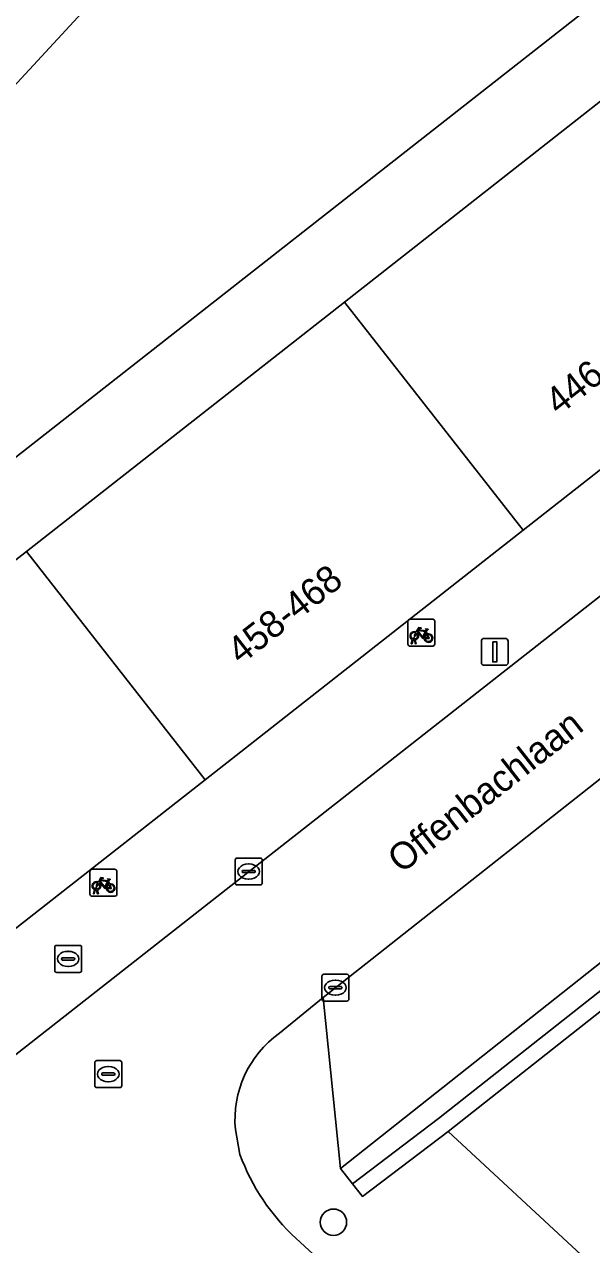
# Model space of a CAD drawing. Extents: x 159217 to 160349, y 381246 to 382172.
# Drawn here: x 159639.79 to 159660.85, y 381595.69 to 381640.95 of the extents above; entities that cross this region are included whole.
import ezdxf

# ---------------------------------------------------------------- set-up
doc = ezdxf.new("R2010")
doc.units = 0
for name, color, linetype in [('IMGEO_Boom', 7, 'Continuous'), ('IMGEO_Brandkraan', 7, 'Continuous'), ('IMGEO_Fietsenrek', 7, 'Continuous'), ('IMGEO_Groenvoorziening', 7, 'Continuous'), ('IMGEO_Haag', 7, 'Continuous'), ('IMGEO_Kolk', 7, 'Continuous'), ('IMGEO_Lichtmast', 7, 'Continuous'), ('IMGEO_Openbare_ruimte_label', 7, 'Continuous'), ('IMGEO_Pand', 7, 'Continuous'), ('IMGEO_Pand_nummerreeks', 7, 'Continuous'), ('IMGEO_Parkeervlak_open', 7, 'Continuous'), ('IMGEO_Rijbaan_lokaal_open', 7, 'Continuous'), ('IMGEO_Rioolput', 7, 'Continuous'), ('IMGEO_Voetpad_open', 7, 'Continuous')]:
    doc.layers.add(name, color=color, linetype=linetype)

msp = doc.modelspace()

# ---------------------------------------------------------------- linework, layer by layer
at = {"layer": 'IMGEO_Boom'}
msp.add_circle((159651.269, 381596.525), 0.489, dxfattribs=at)
at = {"layer": 'IMGEO_Brandkraan'}
for p, q in [((159640.919, 381605.866), (159640.919, 381606.718)), ((159640.994, 381606.792), (159641.846, 381606.792)), ((159641.407, 381606.572), (159641.432, 381606.572)), ((159641.92, 381606.718), (159641.92, 381605.866)), ((159641.178, 381606.286), (159641.178, 381606.298)), ((159641.616, 381606.249), (159641.218, 381606.249)), ((159641.221, 381606.335), (159641.619, 381606.335)), ((159641.662, 381606.298), (159641.662, 381606.286)), ((159641.846, 381605.792), (159640.994, 381605.792)), ((159641.43, 381606.012), (159641.405, 381606.012))]:
    msp.add_line(p, q, dxfattribs=at)
for points in [[(159640.919, 381605.866), (159640.919, 381606.718)], [(159640.994, 381606.792), (159641.846, 381606.792)], [(159641.92, 381606.718), (159641.92, 381605.866)], [(159641.846, 381605.792), (159640.994, 381605.792)]]:
    msp.add_lwpolyline(points, dxfattribs=at)
for centre, radius, start, end in [((159640.996, 381606.716), 0.0765, 91.552, 178.448), ((159640.996, 381606.716), 0.0765, 91.552, 178.448), ((159641.844, 381606.716), 0.0765, 1.552, 88.448), ((159641.844, 381606.716), 0.0765, 1.552, 88.448), ((159641.218, 381606.295), 0.0403, 85.8775, 175.7526), ((159641.215, 381606.285), 0.0366, 178.938, 274.7102), ((159641.619, 381606.292), 0.043, 264.8664, 352.4533), ((159641.623, 381606.297), 0.0386, 1.7309, 96.639), ((159640.996, 381605.868), 0.0765, 181.552, 268.448), ((159640.996, 381605.868), 0.0765, 181.552, 268.448), ((159641.844, 381605.868), 0.0765, 271.552, 358.448), ((159641.844, 381605.868), 0.0765, 271.552, 358.448)]:
    msp.add_arc(centre, radius, start, end, dxfattribs=at)
for centre, major_axis, ratio, start_param, end_param in [((159641.406, 381606.292), (-0.387, 0.002), 0.722429, 4.712389, 7.853982), ((159641.431, 381606.292), (-0.39, 0.002), 0.717154, 1.570796, 4.712389)]:
    msp.add_ellipse(centre, major_axis=major_axis, ratio=ratio, start_param=start_param, end_param=end_param, dxfattribs=at)
at = {"layer": 'IMGEO_Fietsenrek'}
for p, q in [((159654.03, 381617.966), (159654.03, 381618.807)), ((159654.03, 381618.807), (159654.03, 381617.966)), ((159654.105, 381618.891), (159654.946, 381618.891)), ((159654.946, 381618.891), (159654.105, 381618.891)), ((159655.03, 381618.816), (159655.03, 381617.975)), ((159655.03, 381617.975), (159655.03, 381618.816)), ((159654.717, 381618.44), (159654.753, 381618.345)), ((159654.955, 381617.891), (159654.114, 381617.891)), ((159654.114, 381617.891), (159654.955, 381617.891)), ((159654.157, 381617.975), (159654.196, 381618.135)), ((159654.191, 381617.975), (159654.157, 381617.975)), ((159654.226, 381618.123), (159654.191, 381617.975)), ((159654.268, 381618.147), (159654.267, 381618.151)), ((159654.309, 381617.975), (159654.275, 381618.117)), ((159654.299, 381618.158), (159654.3, 381618.151)), ((159654.307, 381618.121), (159654.342, 381617.975)), ((159654.342, 381617.975), (159654.309, 381617.975)), ((159642.228, 381608.692), (159642.228, 381609.533)), ((159642.228, 381609.533), (159642.228, 381608.692)), ((159642.303, 381609.617), (159643.144, 381609.617)), ((159643.144, 381609.617), (159642.303, 381609.617)), ((159643.228, 381609.542), (159643.228, 381608.701)), ((159643.228, 381608.701), (159643.228, 381609.542)), ((159642.355, 381608.701), (159642.394, 381608.861)), ((159642.424, 381608.849), (159642.389, 381608.701)), ((159642.466, 381608.873), (159642.465, 381608.877)), ((159642.507, 381608.701), (159642.473, 381608.843)), ((159642.497, 381608.884), (159642.498, 381608.877)), ((159642.505, 381608.847), (159642.54, 381608.701)), ((159642.915, 381609.166), (159642.951, 381609.071)), ((159643.153, 381608.617), (159642.312, 381608.617)), ((159642.312, 381608.617), (159643.153, 381608.617)), ((159642.389, 381608.701), (159642.355, 381608.701)), ((159642.54, 381608.701), (159642.507, 381608.701))]:
    msp.add_line(p, q, dxfattribs=at)
for points in [[(159654.364, 381618.365), (159654.312, 381618.275), (159654.272, 381618.25), (159654.273, 381618.297), (159654.328, 381618.391)], [(159654.343, 381618.417), (159654.438, 381618.581), (159654.524, 381618.567), (159654.526, 381618.558), (159654.47, 381618.547), (159654.443, 381618.502), (159654.699, 381618.461)], [(159654.639, 381618.173), (159654.589, 381618.173), (159654.398, 381618.424), (159654.379, 381618.392)], [(159654.686, 381618.436), (159654.429, 381618.477), (159654.412, 381618.448), (159654.579, 381618.228), (159654.686, 381618.436)], [(159654.734, 381618.338), (159654.704, 381618.415), (159654.595, 381618.197), (159654.638, 381618.197)], [(159654.668, 381618.197), (159654.788, 381618.196), (159654.744, 381618.31)], [(159654.764, 381618.317), (159654.819, 381618.172), (159654.669, 381618.172)], [(159654.699, 381618.461), (159654.724, 381618.51), (159654.718, 381618.514), (159654.695, 381618.518), (159654.683, 381618.525), (159654.682, 381618.528), (159654.684, 381618.533), (159654.779, 381618.518), (159654.781, 381618.508), (159654.771, 381618.495), (159654.759, 381618.489), (159654.745, 381618.495), (159654.717, 381618.44)], [(159642.541, 381609.143), (159642.636, 381609.307), (159642.722, 381609.293), (159642.724, 381609.284), (159642.668, 381609.273), (159642.641, 381609.228), (159642.897, 381609.187)], [(159642.884, 381609.162), (159642.627, 381609.203), (159642.61, 381609.174), (159642.777, 381608.954), (159642.884, 381609.162)], [(159642.897, 381609.187), (159642.922, 381609.236), (159642.916, 381609.24), (159642.893, 381609.244), (159642.881, 381609.251), (159642.88, 381609.254), (159642.882, 381609.259), (159642.977, 381609.244), (159642.979, 381609.234), (159642.969, 381609.221), (159642.957, 381609.215), (159642.943, 381609.221), (159642.915, 381609.166)], [(159642.562, 381609.091), (159642.51, 381609.001), (159642.47, 381608.976), (159642.471, 381609.023), (159642.526, 381609.117)], [(159642.837, 381608.899), (159642.787, 381608.899), (159642.596, 381609.15), (159642.577, 381609.118)], [(159642.932, 381609.064), (159642.902, 381609.141), (159642.793, 381608.923), (159642.836, 381608.923)], [(159642.866, 381608.923), (159642.986, 381608.922), (159642.942, 381609.036)], [(159642.962, 381609.043), (159643.017, 381608.898), (159642.867, 381608.898)]]:
    msp.add_lwpolyline(points, dxfattribs=at)
for centre, radius, start, end in [((159654.108, 381618.813), 0.0779, 92.4484, 184.2845), ((159654.108, 381618.813), 0.0779, 92.4484, 184.2845), ((159654.952, 381618.813), 0.0779, 2.4484, 94.2845), ((159654.952, 381618.813), 0.0779, 2.4484, 94.2845), ((159654.27, 381618.276), 0.159, 62.6766, 242.1369), ((159654.27, 381618.276), 0.129, 63.3192, 238.903), ((159654.27, 381618.276), 0.129, 283.6043, 43.4302), ((159654.27, 381618.276), 0.159, 283.5766, 46.6042), ((159654.797, 381618.192), 0.159, 113.3408, 178.3217), ((159654.797, 381618.192), 0.159, 187.0065, 105.7708), ((159654.797, 381618.192), 0.129, 113.923, 177.9556), ((159654.797, 381618.192), 0.129, 188.6715, 104.5883), ((159654.108, 381617.969), 0.0779, 182.4484, 274.2845), ((159654.108, 381617.969), 0.0779, 182.4484, 274.2845), ((159654.25, 381618.147), 0.0499, 12.8025, 158.6934), ((159654.27, 381618.276), 0.159, 253.9967, 271.7867), ((159654.25, 381618.147), 0.0174, 12.8025, 163.4502), ((159654.27, 381618.276), 0.129, 253.415, 269.0204), ((159654.952, 381617.969), 0.0779, 272.4484, 4.2845), ((159654.952, 381617.969), 0.0779, 272.4484, 4.2845), ((159642.306, 381609.539), 0.0779, 92.4484, 184.2845), ((159642.306, 381609.539), 0.0779, 92.4484, 184.2845), ((159643.15, 381609.539), 0.0779, 2.4484, 94.2845), ((159643.15, 381609.539), 0.0779, 2.4484, 94.2845), ((159642.468, 381609.002), 0.159, 62.6766, 242.1369), ((159642.468, 381609.002), 0.129, 63.3192, 238.903), ((159642.448, 381608.873), 0.0499, 12.8025, 158.6934), ((159642.468, 381609.002), 0.159, 253.9967, 271.7867), ((159642.448, 381608.873), 0.0174, 12.8025, 163.4502), ((159642.468, 381609.002), 0.129, 253.415, 269.0204), ((159642.468, 381609.002), 0.129, 283.6043, 43.4302), ((159642.468, 381609.002), 0.159, 283.5766, 46.6042), ((159642.995, 381608.918), 0.159, 113.3408, 178.3217), ((159642.995, 381608.918), 0.159, 187.0065, 105.7708), ((159642.995, 381608.918), 0.129, 113.923, 177.9556), ((159642.995, 381608.918), 0.129, 188.6715, 104.5883), ((159642.306, 381608.695), 0.0779, 182.4484, 274.2845), ((159642.306, 381608.695), 0.0779, 182.4484, 274.2845), ((159643.15, 381608.695), 0.0779, 272.4484, 4.2845), ((159643.15, 381608.695), 0.0779, 272.4484, 4.2845)]:
    msp.add_arc(centre, radius, start, end, dxfattribs=at)
at = {"layer": 'IMGEO_Groenvoorziening'}
for points in [[(159671.617, 381650.084), (159666.99, 381662.045), (159665.232, 381666.59), (159621.019, 381618.793), (159625.084, 381613.639)], [(159663.487, 381639.906), (159672.749, 381647.16), (159671.617, 381650.084), (159625.084, 381613.639), (159634.254, 381602.013), (159635.387, 381602.787), (159634.693, 381603.69), (159628.06, 381612.159), (159639.869, 381621.408), (159651.678, 381630.657)], [(159692.005, 381604.643), (159690.074, 381606.457), (159682.249, 381613.809), (159680.462, 381615.488), (159678.112, 381617.696), (159666.889, 381608.847), (159664.757, 381607.166), (159661.453, 381604.561), (159655.531, 381599.891), (159667.442, 381588.844), (159673.929, 381582.827), (159675.769, 381581.12), (159687.565, 381570.179), (159706.244, 381585.938), (159705.893, 381586.316), (159707.664, 381587.959), (159708.044, 381587.55), (159709.165, 381588.521), (159704.338, 381593.056)], [(159664.757, 381607.166), (159664.377, 381607.63), (159661.081, 381605.032), (159655.164, 381600.366), (159651.979, 381597.953), (159652.351, 381597.482), (159655.531, 381599.891), (159661.453, 381604.561)]]:
    msp.add_lwpolyline(points, close=True, dxfattribs=at)
for points in [[(159655.531, 381599.891), (159652.351, 381597.482), (159651.979, 381597.953), (159651.529, 381598.511), (159650.881, 381604.861), (159649.263, 381603.536)], [(159647.629, 381599.962), (159647.794, 381599.04)], [(159649.883, 381595.917), (159652.392, 381593.608), (159653.239, 381592.829), (159659.239, 381587.321), (159666.781, 381587.598), (159666.437, 381587.895), (159667.442, 381588.844), (159655.531, 381599.891)]]:
    msp.add_lwpolyline(points, dxfattribs=at)
for centre, radius, start, end in [((159651.555, 381600.328), 3.943, 125.5416, 185.3195), ((159655.353, 381601.836), 8.059, 200.2988, 227.2589)]:
    msp.add_arc(centre, radius, start, end, dxfattribs=at)
at = {"layer": 'IMGEO_Haag'}
msp.add_lwpolyline([(159664.757, 381607.166), (159664.377, 381607.63), (159661.081, 381605.032), (159655.164, 381600.366), (159651.979, 381597.953), (159652.351, 381597.482), (159655.531, 381599.891), (159661.453, 381604.561)], close=True, dxfattribs=at)
at = {"layer": 'IMGEO_Kolk'}
for p, q in [((159647.622, 381609.107), (159647.622, 381609.959)), ((159647.697, 381610.033), (159648.549, 381610.033)), ((159648.11, 381609.813), (159648.135, 381609.813)), ((159648.623, 381609.959), (159648.623, 381609.107)), ((159647.881, 381609.527), (159647.881, 381609.539)), ((159648.319, 381609.49), (159647.921, 381609.49)), ((159647.924, 381609.576), (159648.322, 381609.576)), ((159648.133, 381609.253), (159648.108, 381609.253)), ((159648.365, 381609.539), (159648.365, 381609.527)), ((159648.549, 381609.033), (159647.697, 381609.033)), ((159650.841, 381604.798), (159650.841, 381605.65)), ((159650.916, 381605.724), (159651.768, 381605.724)), ((159651.842, 381605.65), (159651.842, 381604.798)), ((159651.1, 381605.218), (159651.1, 381605.23)), ((159651.538, 381605.181), (159651.14, 381605.181)), ((159651.143, 381605.267), (159651.541, 381605.267)), ((159651.329, 381605.504), (159651.354, 381605.504)), ((159651.584, 381605.23), (159651.584, 381605.218)), ((159651.768, 381604.724), (159650.916, 381604.724)), ((159651.352, 381604.944), (159651.327, 381604.944))]:
    msp.add_line(p, q, dxfattribs=at)
for points in [[(159647.622, 381609.107), (159647.622, 381609.959)], [(159647.697, 381610.033), (159648.549, 381610.033)], [(159648.623, 381609.959), (159648.623, 381609.107)], [(159648.549, 381609.033), (159647.697, 381609.033)], [(159650.841, 381604.798), (159650.841, 381605.65)], [(159650.916, 381605.724), (159651.768, 381605.724)], [(159651.842, 381605.65), (159651.842, 381604.798)], [(159651.768, 381604.724), (159650.916, 381604.724)]]:
    msp.add_lwpolyline(points, dxfattribs=at)
for centre, radius, start, end in [((159647.699, 381609.957), 0.0765, 91.552, 178.448), ((159647.699, 381609.957), 0.0765, 91.552, 178.448), ((159648.547, 381609.957), 0.0765, 1.552, 88.448), ((159648.547, 381609.957), 0.0765, 1.552, 88.448), ((159647.921, 381609.536), 0.0403, 85.8775, 175.7526), ((159647.918, 381609.526), 0.0366, 178.938, 274.7102), ((159648.322, 381609.533), 0.043, 264.8664, 352.4533), ((159648.326, 381609.538), 0.0386, 1.7309, 96.639), ((159647.699, 381609.109), 0.0765, 181.552, 268.448), ((159647.699, 381609.109), 0.0765, 181.552, 268.448), ((159648.547, 381609.109), 0.0765, 271.552, 358.448), ((159648.547, 381609.109), 0.0765, 271.552, 358.448), ((159650.918, 381605.648), 0.0765, 91.552, 178.448), ((159650.918, 381605.648), 0.0765, 91.552, 178.448), ((159651.766, 381605.648), 0.0765, 1.552, 88.448), ((159651.766, 381605.648), 0.0765, 1.552, 88.448), ((159651.14, 381605.227), 0.0403, 85.8775, 175.7526), ((159651.137, 381605.217), 0.0366, 178.938, 274.7102), ((159651.541, 381605.224), 0.043, 264.8664, 352.4533), ((159651.545, 381605.229), 0.0386, 1.7309, 96.639), ((159650.918, 381604.8), 0.0765, 181.552, 268.448), ((159650.918, 381604.8), 0.0765, 181.552, 268.448), ((159651.766, 381604.8), 0.0765, 271.552, 358.448), ((159651.766, 381604.8), 0.0765, 271.552, 358.448)]:
    msp.add_arc(centre, radius, start, end, dxfattribs=at)
for centre, major_axis, ratio, start_param, end_param in [((159648.109, 381609.533), (-0.387, 0.002), 0.722429, 4.712389, 7.853982), ((159648.134, 381609.533), (-0.39, 0.002), 0.717154, 1.570796, 4.712389), ((159651.328, 381605.224), (-0.387, 0.002), 0.722429, 4.712389, 7.853982), ((159651.353, 381605.224), (-0.39, 0.002), 0.717154, 1.570796, 4.712389)]:
    msp.add_ellipse(centre, major_axis=major_axis, ratio=ratio, start_param=start_param, end_param=end_param, dxfattribs=at)
at = {"layer": 'IMGEO_Lichtmast'}
for p, q in [((159656.763, 381617.281), (159656.763, 381618.081)), ((159656.763, 381618.081), (159656.763, 381617.281)), ((159656.863, 381618.181), (159657.653, 381618.181)), ((159657.653, 381618.181), (159656.863, 381618.181)), ((159657.753, 381618.081), (159657.753, 381617.281)), ((159657.753, 381617.281), (159657.753, 381618.081)), ((159657.653, 381617.181), (159656.863, 381617.181)), ((159656.863, 381617.181), (159657.653, 381617.181))]:
    msp.add_line(p, q, dxfattribs=at)
msp.add_lwpolyline([(159657.183, 381618.056), (159657.333, 381618.056), (159657.333, 381617.306), (159657.183, 381617.306), (159657.183, 381618.056)], dxfattribs=at)
for centre, start, end in [((159656.863, 381618.081), 90, 180), ((159656.863, 381618.081), 90, 180), ((159657.653, 381618.081), 0, 90), ((159657.653, 381618.081), 360, 90), ((159656.863, 381617.281), 180, 270), ((159656.863, 381617.281), 180, 270), ((159657.653, 381617.281), 270, 0), ((159657.653, 381617.281), 270, 0)]:
    msp.add_arc(centre, 0.1, start, end, dxfattribs=at)
at = {"layer": 'IMGEO_Pand'}
for points in [[(159663.487, 381639.906), (159651.678, 381630.657), (159658.311, 381622.189), (159670.12, 381631.438)], [(159646.502, 381612.939), (159658.311, 381622.189), (159651.678, 381630.657), (159639.869, 381621.408)], [(159646.502, 381612.939), (159639.869, 381621.408), (159628.06, 381612.159), (159634.693, 381603.69)]]:
    msp.add_lwpolyline(points, close=True, dxfattribs=at)
at = {"layer": 'IMGEO_Parkeervlak_open'}
msp.add_lwpolyline([(159650.881, 381604.861), (159651.529, 381598.511), (159665.962, 381609.923), (159666.976, 381617.546)], close=True, dxfattribs=at)
at = {"layer": 'IMGEO_Rijbaan_lokaal_open'}
for points in [[(159674.232, 381629.981), (159638.593, 381602.067), (159634.829, 381599.144), (159634.101, 381598.548), (159633.318, 381598.016), (159632.49, 381597.556), (159631.625, 381597.172), (159630.728, 381596.866), (159632.391, 381594.75)], [(159649.263, 381603.536), (159650.881, 381604.861), (159666.976, 381617.546), (159675.488, 381624.14)], [(159647.794, 381599.04), (159647.629, 381599.962)], [(159682.752, 381566.058), (159681.969, 381566.632), (159679.193, 381569.297), (159659.239, 381587.321), (159653.239, 381592.829), (159652.392, 381593.608), (159649.883, 381595.917)]]:
    msp.add_lwpolyline(points, dxfattribs=at)
for centre, radius, start, end in [((159651.555, 381600.328), 3.943, 125.5416, 185.3195), ((159655.353, 381601.836), 8.059, 200.2988, 227.2589)]:
    msp.add_arc(centre, radius, start, end, dxfattribs=at)
at = {"layer": 'IMGEO_Rioolput'}
for p, q in [((159642.408, 381601.591), (159642.408, 381602.443)), ((159642.483, 381602.517), (159643.335, 381602.517)), ((159643.409, 381602.443), (159643.409, 381601.591)), ((159642.667, 381602.011), (159642.667, 381602.023)), ((159643.105, 381601.974), (159642.707, 381601.974)), ((159642.71, 381602.06), (159643.108, 381602.06)), ((159642.896, 381602.297), (159642.921, 381602.297)), ((159643.151, 381602.023), (159643.151, 381602.011)), ((159643.335, 381601.517), (159642.483, 381601.517)), ((159642.919, 381601.737), (159642.894, 381601.737))]:
    msp.add_line(p, q, dxfattribs=at)
for points in [[(159642.408, 381601.591), (159642.408, 381602.443)], [(159642.483, 381602.517), (159643.335, 381602.517)], [(159643.409, 381602.443), (159643.409, 381601.591)], [(159643.335, 381601.517), (159642.483, 381601.517)]]:
    msp.add_lwpolyline(points, dxfattribs=at)
for centre, radius, start, end in [((159642.485, 381602.441), 0.0765, 91.552, 178.448), ((159642.485, 381602.441), 0.0765, 91.552, 178.448), ((159643.333, 381602.441), 0.0765, 1.552, 88.448), ((159643.333, 381602.441), 0.0765, 1.552, 88.448), ((159642.707, 381602.02), 0.0403, 85.8775, 175.7526), ((159642.704, 381602.01), 0.0366, 178.938, 274.7102), ((159643.108, 381602.017), 0.043, 264.8664, 352.4533), ((159643.112, 381602.022), 0.0386, 1.7309, 96.639), ((159642.485, 381601.593), 0.0765, 181.552, 268.448), ((159642.485, 381601.593), 0.0765, 181.552, 268.448), ((159643.333, 381601.593), 0.0765, 271.552, 358.448), ((159643.333, 381601.593), 0.0765, 271.552, 358.448)]:
    msp.add_arc(centre, radius, start, end, dxfattribs=at)
for centre, major_axis, ratio, start_param, end_param in [((159642.895, 381602.017), (-0.387, 0.002), 0.722429, 4.712389, 7.853982), ((159642.92, 381602.017), (-0.39, 0.002), 0.717154, 1.570796, 4.712389)]:
    msp.add_ellipse(centre, major_axis=major_axis, ratio=ratio, start_param=start_param, end_param=end_param, dxfattribs=at)
at = {"layer": 'IMGEO_Voetpad_open'}
for points in [[(159715.613, 381721.211), (159720.635, 381726.662), (159721.887, 381728.002), (159724.688, 381731.045), (159742.186, 381750), (159766.379, 381776.207), (159771.217, 381781.437), (159768.968, 381783.54), (159738.017, 381750), (159653.897, 381658.843), (159629.643, 381632.69), (159615.553, 381617.498), (159615.445, 381617.382), (159608.003, 381609.357), (159604.58, 381605.65), (159606.917, 381603.647), (159616.639, 381614.101), (159619.494, 381617.187), (159621.019, 381618.793), (159665.232, 381666.59), (159670.058, 381671.807), (159670.392, 381672.168), (159671.682, 381673.529), (159674.596, 381676.692)], [(159664.377, 381607.63), (159664.757, 381607.166), (159666.889, 381608.847), (159665.962, 381609.923), (159651.529, 381598.511), (159651.979, 381597.953), (159655.164, 381600.366), (159661.081, 381605.032)]]:
    msp.add_lwpolyline(points, close=True, dxfattribs=at)
msp.add_lwpolyline([(159670.12, 381631.438), (159658.311, 381622.189), (159646.502, 381612.939), (159634.693, 381603.69), (159635.387, 381602.787), (159634.254, 381602.013), (159632.879, 381600.779), (159632.581, 381600.562), (159629.561, 381598.367), (159630.49, 381597.169), (159630.728, 381596.866), (159631.625, 381597.172), (159632.49, 381597.556), (159633.318, 381598.016), (159634.101, 381598.548), (159634.829, 381599.144), (159638.593, 381602.067), (159674.232, 381629.981)], dxfattribs=at)

# ---------------------------------------------------------------- texts
at = {"layer": 'IMGEO_Openbare_ruimte_label'}
msp.add_text('Offenbachlaan', height=1, rotation=38.1765, dxfattribs=at).set_placement((159653.785, 381609.431))
at = {"layer": 'IMGEO_Pand_nummerreeks'}
for s, p in [('446-456', (159659.631, 381626.424)), ('458-468', (159647.825, 381617.176))]:
    msp.add_text(s, height=1, rotation=38.0696, dxfattribs=at).set_placement(p)

doc.saveas('drawing.dxf')
